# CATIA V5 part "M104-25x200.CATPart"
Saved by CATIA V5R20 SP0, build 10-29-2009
Part number: M104-25x200
Source: Unknown
Bounding box of the stored display mesh (mm): x -12.497 to 12.497, y -12.358 to 12.358, z 0 to 200
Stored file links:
  C:\Users\Utente\Desktop\IO LAVORO\3D X SITO CF\X SITO\M104\M104-25x200.CATPart

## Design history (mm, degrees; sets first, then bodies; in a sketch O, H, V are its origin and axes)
Body1 (main body)
  Solid1 "PartBody": solid without history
